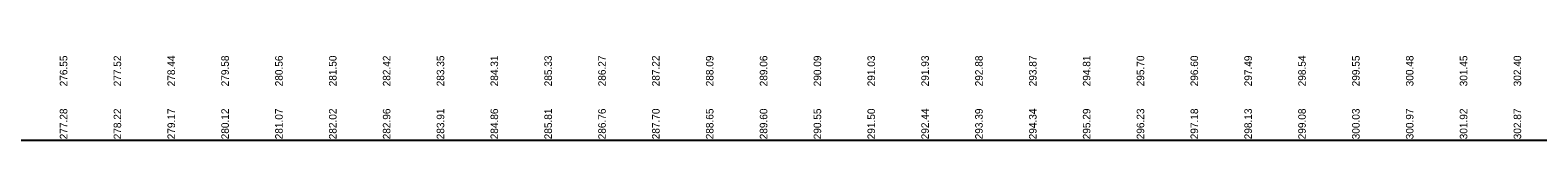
# Model space of a CAD drawing. Extents: x 1876258 to 1932803, y 754739 to 837911.
# Drawn here: x 1889828 to 1891228, y 827963 to 828041 of the extents above; entities that cross this region are included whole.
import ezdxf

# ---------------------------------------------------------------- set-up
doc = ezdxf.new("R2010")
doc.units = 0
doc.layers.add('RD_DDB_StripGrade', color=7, linetype='Continuous')
doc.layers.add('RD_GPK_Profile_Cell', color=7, linetype='Continuous')

msp = doc.modelspace()

# ---------------------------------------------------------------- linework, layer by layer
at = {"layer": 'RD_GPK_Profile_Cell'}
msp.add_line((1878363.1, 827962.8), (1926563.1, 827962.8), dxfattribs=at)

# ---------------------------------------------------------------- texts
at = {"layer": 'RD_DDB_StripGrade'}
for s, p in [('276.55', (1889862.1, 828012.8)), ('277.52', (1889912.1, 828012.8)), ('278.44', (1889962.1, 828012.8)), ('279.58', (1890012.1, 828012.8)), ('280.56', (1890062.1, 828012.8)), ('281.50', (1890112.1, 828012.8)), ('282.42', (1890162.1, 828012.8)), ('283.35', (1890212.1, 828012.8)), ('284.31', (1890262.1, 828012.8)), ('285.33', (1890312.1, 828012.8)), ('286.27', (1890362.1, 828012.8)), ('287.22', (1890412.1, 828012.8)), ('288.09', (1890462.1, 828012.8)), ('289.06', (1890512.1, 828012.8)), ('290.09', (1890562.1, 828012.8)), ('291.03', (1890612.1, 828012.8)), ('291.93', (1890662.1, 828012.8)), ('292.88', (1890712.1, 828012.8)), ('293.87', (1890762.1, 828012.8)), ('294.81', (1890812.1, 828012.8)), ('295.70', (1890862.1, 828012.8)), ('296.60', (1890912.1, 828012.8)), ('297.49', (1890962.1, 828012.8)), ('298.54', (1891012.1, 828012.8)), ('299.55', (1891062.1, 828012.8)), ('300.48', (1891112.1, 828012.8)), ('301.45', (1891162.1, 828012.8)), ('302.40', (1891212.1, 828012.8)), ('277.28', (1889862.1, 827963.6)), ('278.22', (1889912.1, 827963.6)), ('279.17', (1889962.1, 827963.6)), ('280.12', (1890012.1, 827963.6)), ('281.07', (1890062.1, 827963.6)), ('282.02', (1890112.1, 827963.6)), ('282.96', (1890162.1, 827963.6)), ('283.91', (1890212.1, 827963.6)), ('284.86', (1890262.1, 827963.6)), ('285.81', (1890312.1, 827963.6)), ('286.76', (1890362.1, 827963.6)), ('287.70', (1890412.1, 827963.6)), ('288.65', (1890462.1, 827963.6)), ('289.60', (1890512.1, 827963.6)), ('290.55', (1890562.1, 827963.6)), ('291.50', (1890612.1, 827963.6)), ('292.44', (1890662.1, 827963.6)), ('293.39', (1890712.1, 827963.6)), ('294.34', (1890762.1, 827963.6)), ('295.29', (1890812.1, 827963.6)), ('296.23', (1890862.1, 827963.6)), ('297.18', (1890912.1, 827963.6)), ('298.13', (1890962.1, 827963.6)), ('299.08', (1891012.1, 827963.6)), ('300.03', (1891062.1, 827963.6)), ('300.97', (1891112.1, 827963.6)), ('301.92', (1891162.1, 827963.6)), ('302.87', (1891212.1, 827963.6))]:
    msp.add_text(s, height=7, rotation=90, dxfattribs=at).set_placement(p)

doc.saveas('drawing.dxf')
